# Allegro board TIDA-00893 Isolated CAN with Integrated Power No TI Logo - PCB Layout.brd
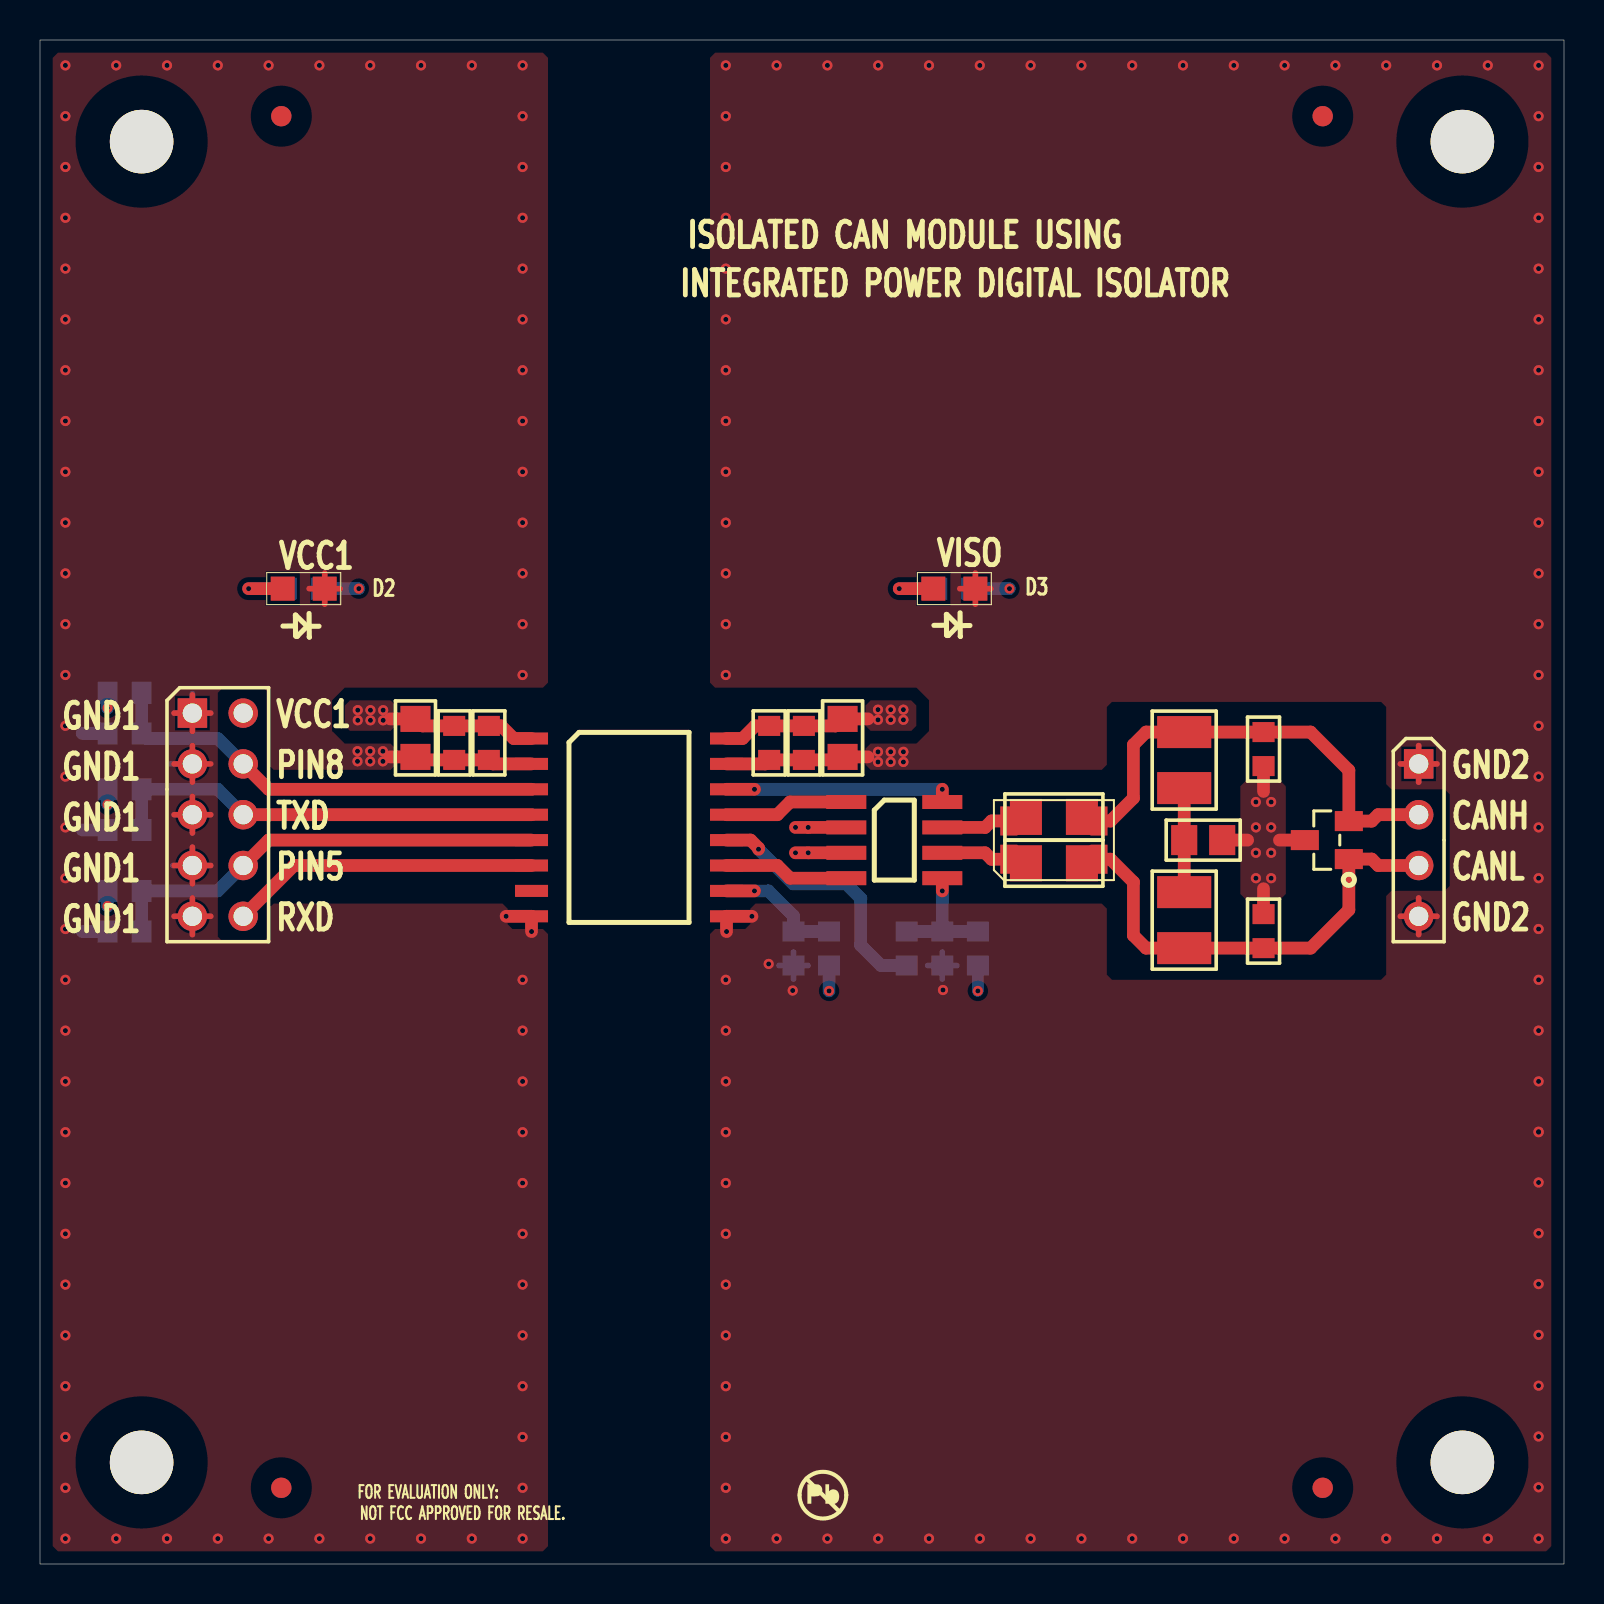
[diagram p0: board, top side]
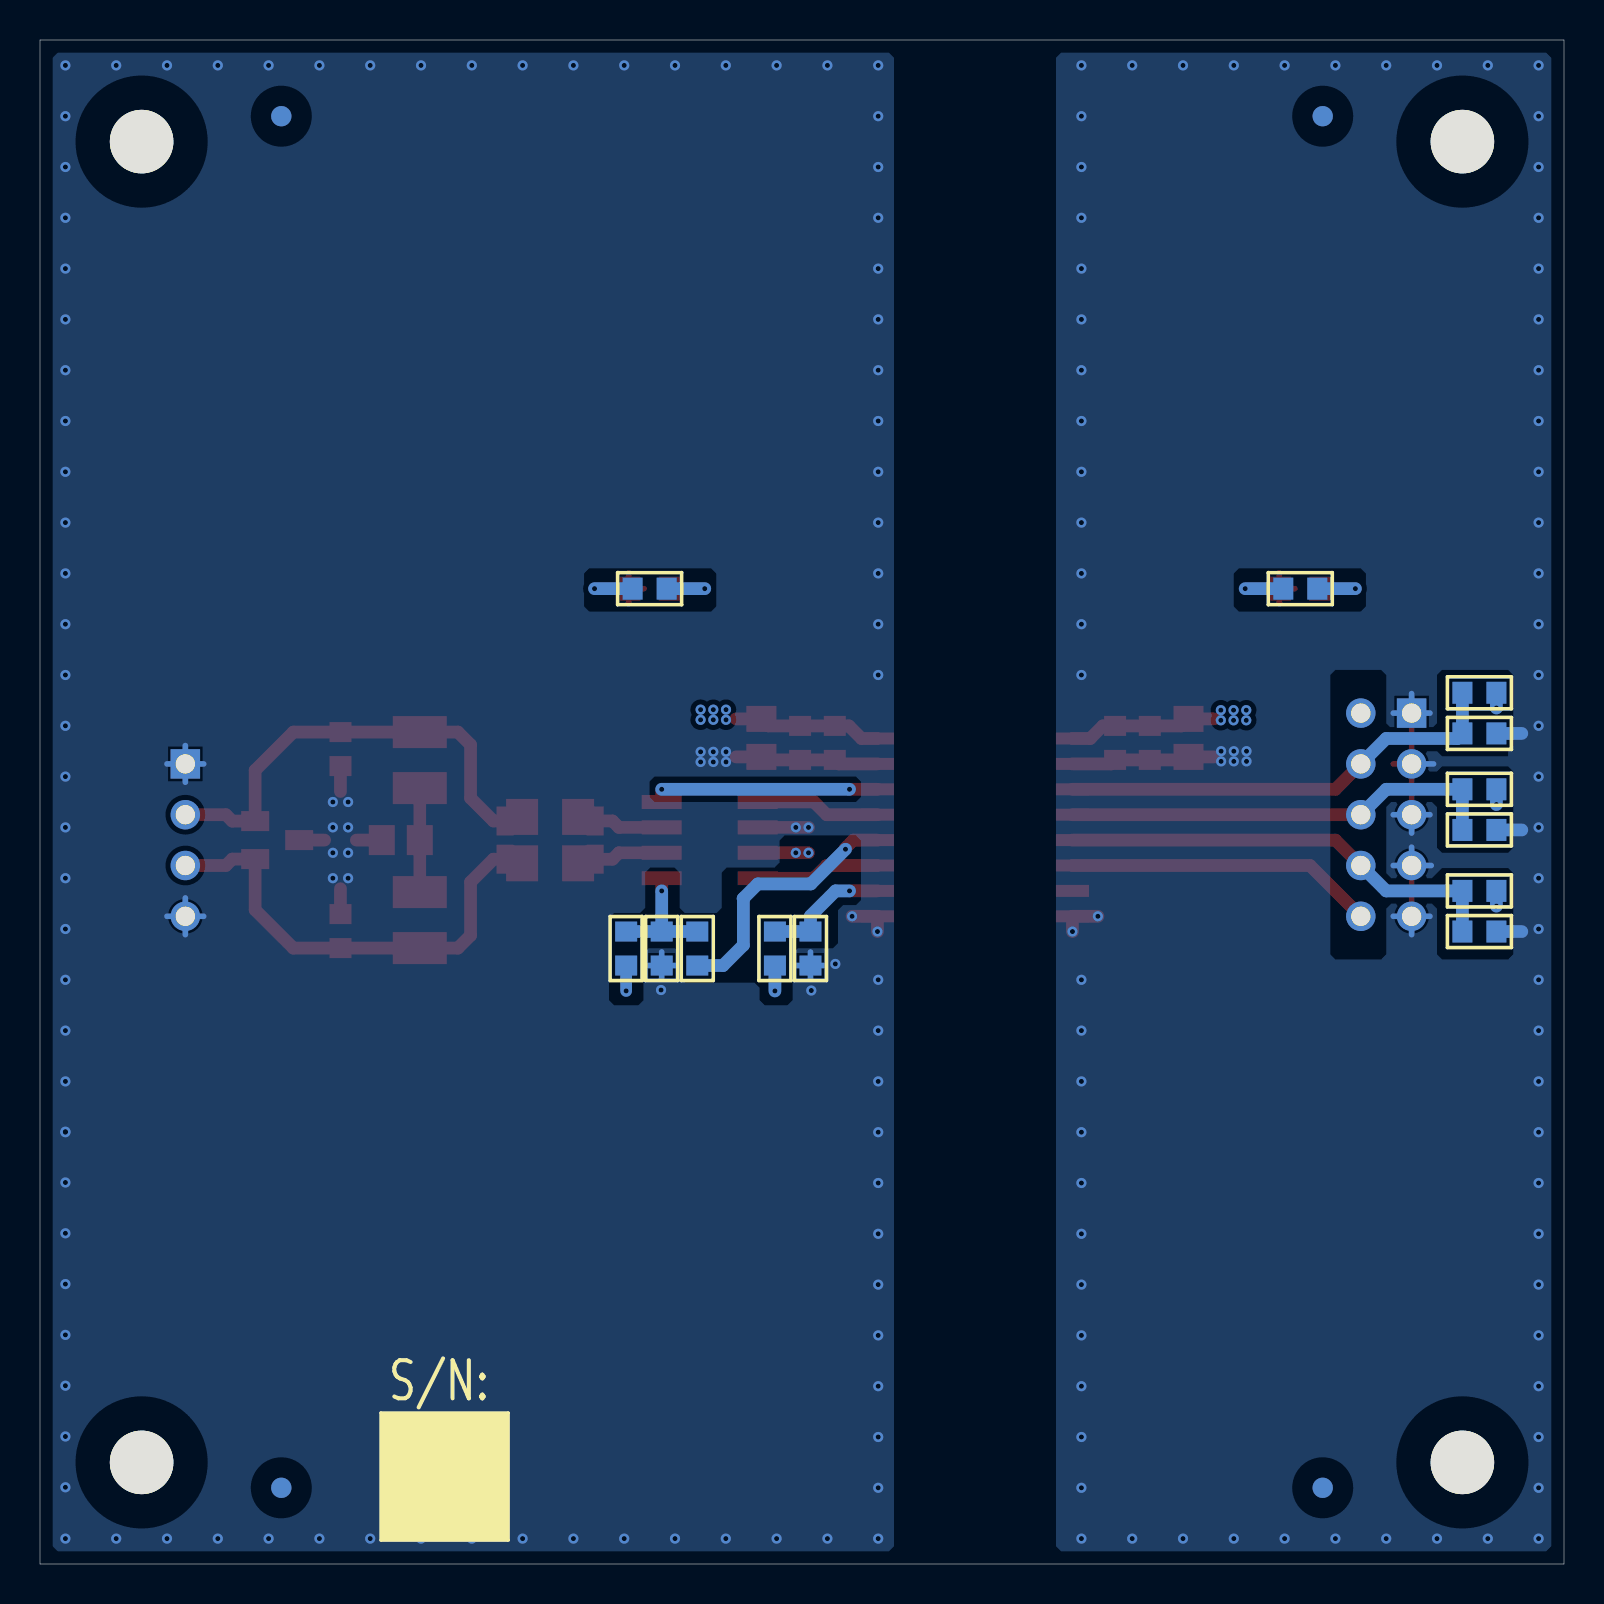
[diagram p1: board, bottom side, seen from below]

Outline 76.2 x 76.2 mm; copper layers: TOP, L2_GND, L3_PWR, BOTTOM. Coordinates in mm from the lower left corner of the outline.
Outline path: 0,76.2 76.2,76.2 76.2,0 0,0 0,76.2

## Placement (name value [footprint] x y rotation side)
C1  10uF  [0805]  18.77 42.25 270 top
C2  1uF  [0603]  20.71 40.2 90 top
C3  .1uF  [0603]  22.44 41.9 270 top
C4  10uF  [0805]  40.13 42.25 270 top
C5  1uF  [0603]  38.19 40.2 90 top
C6  DNI  [0603]  61.18 39.9 90 top
C7  0.1uF  [0603]  36.46 40.2 90 top
C8  0.1uF  [0805]  59.11 36.2 180 top
C9  DNI  [0603]  61.18 32.49 270 top
C10  0.1uF  [0603]  45.12 31.62 270 bottom
D1  DNI  [SOT23]  64.34 36.2 90 top
D2  GREEN  [LED_HSMB_C170DRA]  14.24 48.77 180 top
D3  GREEN  [LED_HSMB_C170DRA]  46.77 48.77 180 top
JMP1  Header 5x2  [HDR_THVT_2X5_100]  7.62 42.55 0 top
JMP2  HEADER 4X1  [HDR_THVT_1X4_100]  68.93 40.01 0 top
L1  DNI-CHOKE CM  [M2022_COMMON-MODE_CHOKE]  50.69 36.2 90 top
NOREF  -  []  0 0 0 top
NOREF#2  -  [unnamed#2]  71.12 71.12 0 top
NOREF#3  -  []  0 0 0 top
NOREF#4  -  []  39.17 3.47 0 top
NOREF#5  -  [unnamed#2]  64.14 3.81 0 top
NOREF#6  -  [unnamed#2]  12.06 3.81 0 top
NOREF#7  -  [unnamed#2]  5.08 5.08 0 top
NOREF#8  -  []  0 0 90 top
NOREF#9  -  [unnamed#2]  12.06 72.39 0 top
NOREF#10  -  [unnamed#2]  5.08 71.12 0 top
NOREF#11  -  []  54.8 6.96 0 top
NOREF#12  -  [unnamed#2]  64.14 72.39 0 top
NOREF#13  -  [unnamed#2]  71.12 5.08 0 top
NOREF#14  -  []  66.13 4.37 180 bottom
NOREF#15  -  [unnamed#2]  64.14 3.81 180 bottom
NOREF#16  -  [unnamed#2]  12.06 72.39 180 bottom
NOREF#17  -  [unnamed#2]  12.06 3.81 180 bottom
NOREF#18  -  [unnamed#2]  64.14 72.39 180 bottom
R1  4.99K  [0603]  5.08 43.56 180 bottom
R2  4.99K  [0603]  5.08 38.73 180 bottom
R3  4.99K  [0603]  5.08 33.66 180 bottom
R4  0-Ohm  [1206]  49.29 37.35 0 top
R5  60  [1210]  57.21 38.8 90 top
R6  60  [1210]  57.21 33.59 270 top
R7  DNI  [0603]  3.38 41.53 0 bottom
R8  DNI  [0603]  3.38 36.7 0 bottom
R9  DNI  [0603]  3.38 31.62 0 bottom
R10  0-Ohm  [0603]  39.45 31.62 270 bottom
R11  0-Ohm  [1206]  49.29 35.04 0 top
R12  DNI  [0603]  43.34 29.92 90 bottom
R13  DNI_0  [0603]  37.68 31.62 270 bottom
R14  0-Ohm  [0603]  46.89 29.92 90 bottom
R15  250  [0603]  14.04 48.77 180 bottom
R16  250  [0603]  46.57 48.77 180 bottom
U1  ISOW7841DWR  [DW0016BHV]  29.45 36.83 0 top
U2  TCAN1042  [D8]  42.72 36.2 0 top

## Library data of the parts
C1-C10 = C
D1 = MMBD101LT1_Diode_0
D2 D3 = LED_HSMS
JMP1 = Header 5x2
JMP2 = 4 Pin Berg Jumper
L1 = CHOKE CM14
R1-R14 = R
R15 R16 = r0402
U1 = ISOW7841DWR
U2 = TCAN1042

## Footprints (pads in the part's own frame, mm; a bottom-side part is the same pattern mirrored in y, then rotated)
0603
  rect 1x1.1 smd: 1(0,0) 2(1.7,0)
0805
  rect 1.3x1.5 smd: 1(0,0) 2(1.9,0)
1206
  rect 1.6x1.8 smd: 1(0,0) 2(2.8,0)
1210
  rect 1.6x2.7 smd: 1(0,0) 2(2.8,0)
D8
  rect 2x0.7 smd: 1(-2.4,1.905) 2(-2.4,0.635) 3(-2.4,-0.635) 4(-2.4,-1.905) 5(2.4,-1.905) 6(2.4,-0.635) 7(2.4,0.635) 8(2.4,1.905)
DW0016BHV
  rect 1.65x0.6 smd: 1(-4.875,4.445) 2(-4.875,3.175) 3(-4.875,1.905) 4(-4.875,0.635) 5(-4.875,-0.635) 6(-4.875,-1.905) 7(-4.875,-3.175) 8(-4.875,-4.445) 9(4.875,-4.445) 10(4.875,-3.175) 11(4.875,-1.905) 12(4.875,-0.635) 13(4.875,0.635) 14(4.875,1.905) 15(4.875,3.175) 16(4.875,4.445)
HDR_THVT_1X4_100
  rect 1.473x1.473 hole 0.965: 1(0,0)
  round 1.473 hole 0.965: 2(0,-2.54) 3(0,-5.08) 4(0,-7.62)
HDR_THVT_2X5_100
  rect 1.473x1.473 hole 0.965: 1(0,0)
  round 1.473 hole 0.965: 2(2.54,0) 3(0,-2.54) 4(2.54,-2.54) 5(0,-5.08) 6(2.54,-5.08) 7(0,-7.62) 8(2.54,-7.62) 9(0,-10.16) 10(2.54,-10.16)
LED_HSMB_C170DRA
  rect 1.2x1.2 smd: 1(0,0) 2(2.1,0)
M2022_COMMON-MODE_CHOKE
  custom 0.305x0.305 smd: 1(-0.955,2.07) 2(-0.955,-2.07) 3(0.955,-2.07) 4(0.955,2.07)
SOT23
  rect 1x1.4 smd: 1(-0.95,-1.1) 2(0.95,-1.1) 3(0,1.1)
unnamed#2
  round 3.175 hole 3.175 unplated: (0,0)

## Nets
GND_AC: C1.2 C2.1 C3.2 D2.1 JMP1.1 JMP1.3 JMP1.5 JMP1.7 JMP1.9 R7.1 R8.1 R9.1 U1.2(GND1_1) U1.8(GND1_2)
VCC1: C1.1 C2.2 C3.1 JMP1.2 R1.2 R2.2 R3.2 R15.1 U1.1(VCC1)
VCC1_LED: D2.2 R15.2
CAN_PIN5: C10.1 R12.2 R14.2 U2.5(NC/VIO)
CANH: L1.4 R4.1 U2.7(CANH)
CANH_BUS: C6.2 D1.2(NC) JMP2.2 L1.3 R4.2 R5.2
CANL: L1.1 R11.1 U2.6(CANL)
CANL_BUS: C9.2 D1.1(A) JMP2.3 L1.2 R6.2 R11.2
ISO-PIN5: R12.1 U1.12(OUTC)
ISO-PIN8: U1.14(OUTA) U2.8(S/STB)
ISO-RXD: JMP1.10 U1.6(OUTD)
ISO-TXD: U1.13(OUTB) U2.1(TXD)
PIN5: JMP1.8 R3.1 R9.2 U1.5(INC)
PIN8: JMP1.4 R1.1 R7.2 U1.3(INA)
RXD: U1.11(IND) U2.4(RXD)
SIGNAL_GND_AC: C4.2 C5.1 C6.1 C7.1 C8.1 C9.1 C10.2 D1.3(C) D3.1 JMP2.1 JMP2.4 R13.2 U1.9(GND2_2) U1.15(GND2_1) U2.2(GND)
SPLIT_TERM: C8.2 R5.1 R6.1
TXD: JMP1.6 R2.1 R8.2 U1.4(INB)
VISO: C4.1 C5.2 C7.2 R10.2 R14.1 R16.1 U1.16(VISO) U2.3(VCC)
VISO_LED: D3.2 R16.2
VSEL: R10.1 R13.1 U1.10(SEL)

Pads without a net: U1 7

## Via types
v1: diameter 0.508, hole 0.254, TOP to BOTTOM, 214 vias

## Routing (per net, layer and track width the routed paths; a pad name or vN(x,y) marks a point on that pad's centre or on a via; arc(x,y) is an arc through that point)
GND_AC: length 65
  TOP w0.279: 6.71,40.01 JMP1.3 ; JMP1.3 8.53,40.01 ; JMP1.3 7.62,40.92 ; JMP1.3 7.62,39.09 ; 13.46,48.77 D2.1 ; D2.1 15.01,48.77 ; D2.1 14.24,49.55 ; D2.1 14.24,47.99 ; 6.71,34.92 7.62,34.92 ; 7.62,34.92 7.62,35.84 ; 7.62,34.92 8.53,34.92 ; 7.62,34.92 7.62,34.01 ; 7.62,41.63 JMP1.1 ; JMP1.1 7.62,43.46 ; JMP1.1 6.71,42.55 ; JMP1.1 8.53,42.55 ; 7.62,32.38 8.53,32.38 ; 7.62,32.38 6.71,32.38 ; 7.62,32.38 7.62,31.47 ; 7.62,32.38 7.62,33.3 ; JMP1.5 7.62,38.38 ; JMP1.5 6.71,37.47 ; JMP1.5 7.62,36.55 ; JMP1.5 8.53,37.47
  TOP w0.635: U1.2 22.64,40.01 C3.2 C2.1 18.92,40.2 C1.2 17.5,40.36 ; v1(23.31,32.38) U1.8 v1(24.58,31.62)
  L2_GND w0.279: 7.62,32.38 8.53,32.38 ; 7.62,32.38 7.62,31.47 ; 7.62,32.38 6.71,32.38 ; 7.62,32.38 7.62,33.3 ; 6.71,37.47 JMP1.5 ; JMP1.5 7.62,38.38 ; JMP1.5 8.53,37.47 ; JMP1.5 7.62,36.55 ; JMP1.3 8.53,40.01 ; JMP1.3 7.62,40.92 ; JMP1.3 6.71,40.01 ; JMP1.3 7.62,39.09 ; 7.62,41.63 JMP1.1 ; JMP1.1 8.53,42.55 ; JMP1.1 7.62,43.46 ; JMP1.1 6.71,42.55 ; 7.62,34.92 8.53,34.92 ; 7.62,34.92 7.62,35.84 ; 7.62,34.92 7.62,34.01 ; 7.62,34.92 6.71,34.92
  BOTTOM w0.279: 6.71,42.55 JMP1.1 ; JMP1.1 8.53,42.55 ; JMP1.1 7.62,43.52 ; JMP1.5 8.53,37.47 ; JMP1.5 6.71,37.47 ; JMP1.5 7.62,36.55 ; JMP1.3 6.52,40.01 ; 7.62,31.47 7.62,32.38 ; 7.62,32.38 8.53,32.38 ; 7.62,32.38 6.71,32.38 ; 7.62,34.92 6.64,34.92 ; 7.62,34.92 7.62,35.84 ; 7.62,34.92 8.53,34.92
  BOTTOM w0.635: R7.1 2.11,41.53 ; R9.1 2.11,31.62 ; R8.1 2.11,36.7
  vias: v1(1.27,74.93) v1(1.27,72.39) v1(1.27,69.85) v1(1.27,67.31) v1(1.27,64.77) v1(1.27,62.23) v1(1.27,59.69) v1(1.27,57.15) v1(1.27,54.61) v1(1.27,52.07) v1(1.27,49.53) v1(1.27,46.99) v1(1.27,44.45) v1(1.27,41.91) v1(1.27,39.37) v1(1.27,36.83) v1(1.27,34.29) v1(1.27,31.75) v1(1.27,29.21) v1(1.27,26.67) v1(1.27,24.13) v1(1.27,21.59) v1(1.27,19.05) v1(1.27,16.51) v1(1.27,13.97) v1(1.27,11.43) v1(1.27,8.89) v1(1.27,6.35) v1(1.27,3.81) v1(1.27,1.27) v1(3.81,74.93) v1(3.81,1.27) v1(6.35,74.93) v1(6.35,1.27) v1(8.89,74.93) v1(8.89,1.27) v1(11.43,74.93) v1(11.43,1.27) v1(13.97,74.93) v1(13.97,1.27) v1(15.88,40.64) v1(15.88,40.13) v1(16.51,74.93) v1(16.51,40.64) v1(16.51,40.13) v1(16.51,1.27) v1(17.14,40.64) v1(17.14,40.13) v1(19.05,74.93) v1(19.05,1.27) v1(21.59,74.93) v1(21.59,1.27) v1(24.13,74.93) v1(24.13,72.39) v1(24.13,69.85) v1(24.13,67.31) v1(24.13,64.77) v1(24.13,62.23) v1(24.13,59.69) v1(24.13,57.15) v1(24.13,54.61) v1(24.13,52.07) v1(24.13,49.53) v1(24.13,46.99) v1(24.13,44.45) v1(24.13,29.21) v1(24.13,26.67) v1(24.13,24.13) v1(24.13,21.59) v1(24.13,19.05) v1(24.13,16.51) v1(24.13,13.97) v1(24.13,11.43) v1(24.13,8.89) v1(24.13,6.35) v1(24.13,3.81) v1(24.13,1.27)
VCC1: length 15.3
  TOP w0.635: 17.5,42.25 C1.1 19.12,41.9 C2.2 C3.1 23.06,41.9 23.69,41.27 U1.1
  L3_PWR w0.279: 10.16,41.63 JMP1.2 ; JMP1.2 11.07,42.55 ; JMP1.2 9.25,42.55 ; JMP1.2 10.16,43.46
  BOTTOM w0.635: v1(3.38,32.89) R3.2 ; v1(3.38,37.97) R2.2 ; v1(3.38,42.8) R1.2 ; R15.1 v1(15.94,48.77)
  vias: v1(15.89,42.69) v1(15.89,42.18) v1(16.52,42.69) v1(16.52,42.18) v1(17.16,42.69) v1(17.16,42.18)
VCC1_LED: length 3.6
  TOP w0.635: D2.2 v1(10.43,48.77)
  BOTTOM w0.635: R15.2 v1(10.43,48.77)
CAN_PIN5: length 6.2
  TOP w0.635: v1(45.12,33.66) U2.5
  BOTTOM w0.635: C10.1 v1(45.12,33.66) ; C10.1 R12.2 ; C10.1 R14.2
CANH: length 4.4
  TOP w0.635: U2.7 47.25,36.83 47.58,37.15 48.62,37.15 L1.4 48.83,37.35 R4.1
CANH_BUS: length 23.8
  TOP w0.635: JMP2.2 66.91,37.47 66.59,37.14 D1.2 65.44,39.68 63.53,41.6 C6.2 R5.2 55.31,41.6 54.67,40.96 54.67,38.29 53.53,37.15 L1.3 52.56,37.35 R4.2
CANL: length 4.4
  TOP w0.635: R11.1 48.83,35.04 L1.1 48.62,35.24 47.58,35.24 47.25,35.56 U2.6
CANL_BUS: length 23.8
  TOP w0.635: R11.2 52.56,35.04 L1.2 53.53,35.24 54.67,34.1 54.67,31.43 55.31,30.79 R6.2 C9.2 63.53,30.79 65.44,32.71 D1.1 66.59,35.25 66.91,34.92 68.93,34.92
ISO-PIN5: length 13
  TOP w0.635: v1(35.93,35.74) 35.93,35.8 35.53,36.2 U1.12
  BOTTOM w0.635: v1(35.93,35.74) 37.66,34 40.31,34 41.04,33.27 41.03,33.26 41.03,30.94 42.05,29.92 R12.1
ISO-PIN8: length 11.4
  TOP w0.635: U1.14 v1(35.72,38.73) ; U2.8 v1(45.12,38.73)
  BOTTOM w0.635: v1(35.72,38.73) v1(45.12,38.73)
ISO-RXD: length 15.5
  TOP w0.635: U1.6 12.7,34.92 10.16,32.38
ISO-TXD: length 6.3
  TOP w0.635: U1.13 36.87,37.47 37.5,38.1 U2.1
PIN5: length 22.6
  TOP w0.635: 10.16,34.92 11.43,36.2 U1.5
  BOTTOM w0.635: 10.16,34.92 8.89,33.66 R3.1 R9.2
PIN8: length 22.7
  TOP w0.635: U1.3 11.43,38.73 JMP1.4
  BOTTOM w0.635: JMP1.4 8.89,41.27 5.33,41.27 R7.2 R1.1
RXD: length 6.3
  TOP w0.635: U2.4 37.5,34.29 36.87,34.92 U1.11
SIGNAL_GND_AC: length 47.6
  TOP w0.279: D3.1 46.77,49.55 ; D3.1 46.77,47.99 ; D3.1 45.99,48.77 ; D3.1 47.55,48.77 ; 68.02,32.38 68.93,32.38 ; 68.93,32.38 68.93,31.47 ; 68.93,32.38 68.93,33.3 ; 68.93,32.38 69.85,32.38 ; JMP2.1 69.85,40.01 ; JMP2.1 68.93,39.09 ; JMP2.1 68.93,40.92 ; JMP2.1 68.02,40.01
  TOP w0.635: v1(35.6,32.38) U1.9 v1(34.33,31.62) ; D1.3 61.97,36.2 ; C6.1 61.18,38.63 ; U2.2 v1(38.41,36.83) v1(37.78,36.83) ; U1.15 36.26,40.01 C7.1 C5.1 39.98,40.2 C4.2 41.4,40.36 ; C8.1 60.38,36.2 ; C9.1 61.18,33.76
  L2_GND w0.279: JMP2.1 68.93,40.92 ; JMP2.1 69.85,40.01 ; JMP2.1 68.93,39.09 ; JMP2.1 68.02,40.01 ; 68.02,32.38 68.93,32.38 ; 68.93,32.38 69.85,32.38 ; 68.93,32.38 68.93,31.47 ; 68.93,32.38 68.93,33.3
  BOTTOM w0.279: JMP2.1 69.85,40.01 ; JMP2.1 68.02,40.01 ; JMP2.1 68.93,40.92 ; JMP2.1 68.93,39.09 ; C10.2 45.84,29.92 ; C10.2 45.12,30.6 ; C10.2 44.39,29.92 ; C10.2 45.12,29.24 ; 68.93,32.38 68.93,33.3 ; 68.93,32.38 68.93,31.47 ; 68.93,32.38 69.85,32.38 ; 68.93,32.38 68.02,32.38 ; R13.2 37.68,30.6 ; R13.2 36.95,29.92 ; R13.2 38.4,29.92 ; R13.2 37.68,29.24
  vias: v1(34.29,74.93) v1(34.29,72.39) v1(34.29,69.85) v1(34.29,67.31) v1(34.29,64.77) v1(34.29,62.23) v1(34.29,59.69) v1(34.29,57.15) v1(34.29,54.61) v1(34.29,52.07) v1(34.29,49.53) v1(34.29,46.99) v1(34.29,44.45) v1(34.29,29.21) v1(34.29,26.67) v1(34.29,24.13) v1(34.29,21.59) v1(34.29,19.05) v1(34.29,16.51) v1(34.29,13.97) v1(34.29,11.43) v1(34.29,8.89) v1(34.29,6.35) v1(34.29,3.81) v1(34.29,1.27) v1(36.43,30) v1(36.83,74.93) v1(36.83,1.27) v1(37.64,28.67) v1(39.37,74.93) v1(39.37,1.27) v1(41.91,74.93) v1(41.9,40.61) v1(41.9,40.1) v1(41.91,1.27) v1(42.53,40.61) v1(42.53,40.1) v1(43.17,40.61) v1(43.17,40.1) v1(44.45,74.93) v1(44.45,1.27) v1(45.15,28.7) v1(46.99,74.93) v1(46.99,1.27) v1(49.53,74.93) v1(49.53,1.27) v1(52.07,74.93) v1(52.07,1.27) v1(54.61,74.93) v1(54.61,1.27) v1(57.15,74.93) v1(57.15,1.27) v1(59.69,74.93) v1(59.69,1.27) v1(60.8,38.1) v1(60.8,36.83) v1(60.8,35.56) v1(60.8,34.29) v1(61.56,38.1) v1(61.56,36.83) v1(61.56,35.56) v1(61.56,34.29) v1(62.23,74.93) v1(62.23,1.27) v1(64.77,74.93) v1(64.77,1.27) v1(67.31,74.93) v1(67.31,1.27) v1(69.85,74.93) v1(69.85,1.27) v1(72.39,74.93) v1(72.39,1.27) v1(74.93,74.93) v1(74.93,72.39) v1(74.93,69.85) v1(74.93,67.31) v1(74.93,64.77) v1(74.93,62.23) v1(74.93,59.69) v1(74.93,57.15) v1(74.93,54.61) v1(74.93,52.07) v1(74.93,49.53) v1(74.93,46.99) v1(74.93,44.45) v1(74.93,41.91) v1(74.93,39.37) v1(74.93,36.83) v1(74.93,34.29) v1(74.93,31.75) v1(74.93,29.21) v1(74.93,26.67) v1(74.93,24.13) v1(74.93,21.62) v1(74.93,21.59) v1(74.93,19.08) v1(74.93,16.54) v1(74.93,14) v1(74.93,11.46) v1(74.93,8.92) v1(74.93,6.38) v1(74.93,3.84) v1(74.93,1.27)
SPLIT_TERM: length 5.2
  TOP w0.635: R6.1 C8.2 R5.1
TXD: length 22.1
  TOP w0.635: U1.4 JMP1.6
  BOTTOM w0.635: JMP1.6 8.89,38.73 R2.1 R8.2
VISO: length 14.5
  TOP w0.635: U2.3 v1(38.41,35.56) v1(37.78,35.56) ; 41.4,42.25 C4.1 39.78,41.9 C5.2 C7.2 35.76,41.9 35.13,41.27 U1.16
  BOTTOM w0.584: R14.1 v1(46.89,28.65)
  BOTTOM w0.635: v1(39.45,28.65) R10.2 ; R16.1 v1(48.47,48.77)
  vias: v1(41.9,42.72) v1(41.9,42.21) v1(42.53,42.72) v1(42.53,42.21) v1(43.17,42.72) v1(43.17,42.21)
VISO_LED: length 3.6
  TOP w0.635: D3.2 v1(42.96,48.77)
  BOTTOM w0.635: R16.2 v1(42.96,48.77)
VSEL: length 6.4
  TOP w0.635: v1(35.72,33.66) U1.10
  BOTTOM w0.635: R10.1 R13.1 37.68,32.4 36.42,33.66 v1(35.72,33.66)

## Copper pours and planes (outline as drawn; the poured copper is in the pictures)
GND_AC on TOP: 0.89,0.64 0.64,0.89 0.64,75.31 0.89,75.56 25.15,75.56 25.4,75.31 25.4,44.07 25.15,43.81 16.09,43.81 16.09,41.02 17.53,41.02 17.78,40.77 17.78,39.96 17.53,39.71 11.68,39.71 11.43,39.96 11.43,43.56 11.18,43.81 9.14,43.81 8.89,43.56 8.89,31.37 9.14,31.11 11.18,31.11 11.43,31.37 11.43,32.77 11.68,33.02 23.13,33.02 23.38,32.77 23.38,31.99 23.62,31.75 25.15,31.75 25.4,31.5 25.4,0.89 25.15,0.64
GND_AC on BOTTOM: 0.89,0.64 0.64,0.89 0.64,75.31 0.89,75.56 25.15,75.56 25.4,75.31 25.4,0.89 25.15,0.64 ; 2 cut-outs
GND_AC on L2_GND: 0.89,0.64 0.64,0.89 0.64,75.31 0.89,75.56 25.15,75.56 25.4,75.31 25.4,73.91 25.65,73.66 32.59,73.66 32.84,73.41 32.84,2.79 32.59,2.54 25.65,2.54 25.4,2.29 25.4,0.89 25.15,0.64
VCC1 on TOP: 15.49,41.66 17.53,41.66 17.78,41.91 17.78,42.93 17.53,43.18 15.49,43.18 15.24,42.93 15.24,41.91
VCC1 on L3_PWR: 0.89,0.64 25.15,0.64 25.4,0.89 25.4,75.31 25.15,75.56 0.89,75.56 0.64,75.31 0.64,0.89
SIGNAL_GND_AC on TOP: 60.27,33.25 62.03,33.25 62.29,33.5 62.29,38.89 62.03,39.14 60.27,39.14 60.02,38.89 60.02,33.5
SIGNAL_GND_AC on TOP: 33.75,0.64 33.5,0.89 33.5,31.5 33.75,31.75 35.26,31.75 35.52,32 35.52,32.77 35.77,33.02 53.09,33.02 53.34,32.77 53.34,29.46 53.59,29.21 67.06,29.21 67.31,29.46 67.31,33.4 67.56,33.66 70.23,33.66 70.48,33.91 70.48,38.48 70.23,38.73 67.56,38.73 67.31,38.99 67.31,42.85 67.06,43.1 53.59,43.1 53.34,42.85 53.34,39.96 53.09,39.71 41.53,39.71 41.27,39.96 41.27,40.77 41.53,41.02 42.55,41.02 42.55,43.81 33.75,43.81 33.5,44.07 33.5,75.31 33.75,75.56 75.31,75.56 75.56,75.31 75.56,0.89 75.31,0.64
SIGNAL_GND_AC on BOTTOM: 33.75,0.64 33.5,0.89 33.5,75.31 33.75,75.56 75.31,75.56 75.56,75.31 75.56,0.89 75.31,0.64 ; 3 cut-outs
SIGNAL_GND_AC on L2_GND: 33.75,0.64 75.31,0.64 75.56,0.89 75.56,75.31 75.31,75.56 33.75,75.56 33.5,75.31 33.5,0.89
VISO on TOP: 41.53,41.66 43.56,41.66 43.81,41.91 43.81,42.93 43.56,43.18 41.53,43.18 41.27,42.93 41.27,41.91
VISO on L3_PWR: 33.75,0.64 33.5,0.89 33.5,2.29 33.25,2.54 26.31,2.54 26.06,2.79 26.06,73.41 26.31,73.66 33.25,73.66 33.5,73.91 33.5,75.31 33.75,75.56 75.31,75.56 75.56,75.31 75.56,0.89 75.31,0.64

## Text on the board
BOTTOM: LAYER 4 - BOTTOM SIDE
Ref Des/Assembly Bottom: BOTTOM - ASSEMBLY
Board Geometry/Soldermask Bottom: SOLDERMASK BOTTOM
Package Geometry/Pastemask Bottom: PASTEMASK BOTTOM
Ref Des/Silkscreen Bottom: SILKSCREEN BOTTOM
User.Comments: IN (.XX)+/-0.01 (.XXX)+/-0.003 | MM (.XX)+/-0.01 (.XXX)+/-0.003 | FRACTION  +/- 1/32 | ANGLE  +/- 1.0 DEGREE | THIRD ANGLE PROJECTION | TOLERANCES | UNITS   IN (MM) | UNLESS OTHERWISE SPECIFIED | WWW.TI.COM | 12500 TI BLVD | DALLAS,TX 75243 | TEXAS INSTRUMENTS INC. | THIS DOCUMENT AND THE INFORMATION IN IT | BE DISCLOSED TO ANY THIRD PARTY OR USED | ARE PROVIDED IN CONFIDENCE, FOR THE SOLE | WRITTEN PERMISSION OF TEXAS INSTRUMENTS. | PURPOSE OF BOARD FABRICATION, AND MAY NOT | FOR ANY OTHER PURPOSE WITHOUT THE EXPRESS | TEXAS INSTRUMENTS CONFIDENTIAL
Board Geometry/Outline: BOARD OUTLINE
TOP: LAYER 1 - TOP SIDE
Ref Des/Assembly Top: TOP - ASSEMBLY
Board Geometry/Soldermask Top: SOLDERMASK TOP
Package Geometry/Pastemask Top: PASTEMASK TOP
Ref Des/Silkscreen Top: FOR EVALUATION ONLY: | NOT FCC APPROVED FOR RESALE. | VCC1 | VISO | ISOLATED CAN MODULE USING | INTEGRATED POWER DIGITAL ISOLATOR | SILKSCREEN TOP
L2_GND: LAYER 2 - GND
L3_PWR: LAYER 3 - PWR
XSECTION_CHART: *  SURFACE - AIR 0 MIL | *  DIELECTRIC - SOLDERMASK-0.8MIL 0.8 MIL | L1: TOP CONDUCTOR - 2OZ_COPPER 2.8 MIL | *  DIELECTRIC - FR-4 14 MIL | L2: L2_GND PLANE - 1OZ_COPPER 1.4 MIL | *  DIELECTRIC - FR-4 23.6 MIL | L3: L3_PWR PLANE - 1OZ_COPPER 1.4 MIL | L4: BOTTOM CONDUCTOR - 2OZ_COPPER 2.8 MIL | DESIGN CROSS SECTION CHART | ___________________________ | TOTAL THICKNESS 61.6 MIL | 1-4
PAGE_OUTLINE: J. NERGER | xxx | 01-16-17 | xx-xx-xx | DRAWN: | RELEASED: | DO NOT SCALE DRAWING | APPROVALS | DATE | SIZE | SCALE | CUSTOMER | ID NO. | NONE | JOB NO. | ENGINEER | REV. | TIDA-00893 | BOARD NAME : ISOWATT + TCAN | A | D | C | B | 8 | 7 | 6 | 5 | 4 | 3 | 2 | 1
DIMENSION: FABRICATION DRAWING | CAD ORIGIN
User.6: ALL ARTWORK LAYERS VIEWED FROM TOP | BOARD NAME: | ISOWATT + TCAN REFERENCE DESIGN | BOARD REV: | LAYER DESCRIPTION: | A | ID: | TIDA-00893 | JOB NUMBER:
User.8: LAYER 1 | LAYER 2 | LAYER 3 | LAYER 4 | LAYER | NO. | TABLE 1: | TOP | L2_GND | L3_PWR | BOTTOM | NAME | DIFFIRENTIAL PAIR | IMPEDANCE (OHMS) | DIFF TRACE | WIDTH | SINGLE ENDED | 50 OHMS | TRACE WIDTH | 25 MILS | REFERENCE | SPECIAL FAB NOTES: | 1:FAB SHOP MUST FOLLOW THE SOLDER MASK REVIEW LAYERS. | 2:ADJUSTMENTS MAY BE MADE TO THE DIELECTRIC THICKNESS AND SIGNAL TRACE WIDTH | IN ORDER TO MAINTAIN A TOTAL BOARD THICKNESS. | PLACE DRILL CHART HERE: | MIN. ANNULAR RING 2 MIL EXTERNAL PER IPC-6012C CLASS 2 | REGISTRATION TOLERANCES: METAL +/- X MIL,HOLES +/- X MIL | IMPEDANCE CONTROL: | BOARD SIZE (REFER ALSO ARRAY/PANEL PROFILING INFORMATION) | MIXED DIELECTRIC: | LAMINATE MATERIAL: | THICKNESS: | TOLERANCE: | COPPER THICKNESS (FINISHED): | BOARD FINISH: | NUMBER OF LAYERS: | MIN. TRACK WIDTH: | MIN. CLEARANCE  : | MIN. VIA PAD/DRILL: | THIEVING ALLOWED: | X | OUTER: | INNER SIGNAL: | INNER PLANE: | OTHER: | SILKSCREEN: | SOLDERMASK: (PER IPC-6011,6012) | BOARD SURFACE TREATMENT: | ADDITIONAL REQUIREMENTS: | VENDOR MARKING: | SILKSCREEN COLOR: | SOLDERMASK COLOR: | THROUGH-HOLE VIA TREATMENT: | VIA FILL USING NON-CONDUCTIVE EPOXY: | FOR WIRE BONDING: | VENDOR DATE CODE,UL,LOGO: | FR-4 HIGH Tg | 0.062" +/-10% | IPC-6012C TYPE 3 CLASS 2 | OTHER +/- | MICRO-SECTION | CERTIFICATES OF COMPLIANCE | NICKEL/GOLD (ENIG) | IMMERSION TIN | HARD GOLD | IN AN OPEN AREA | 1/4 OZ. | OPEN | NO | 4 | 11 MIL | X.X MIL | 20/10 MIL | NONE | DESIGN INFORMATION | ROGERS 4350B | 0.093" +/-10% | YES | TDR REPORTS/COUPONS | WHITE | GREEN | SOFT GOLD | TENTED | 1/2 OZ. | BOW & TWIST: | ORGANIC (OSP) | OTHER | WHERE INDICATED (SEE DRAWING) | YES - SEE TABLE 1 | ETCH | IDENTIFIER: | BLUE | RoHS | 1.0 OZ. | SILKSCREEN | PER SUPPLIED ARTWORK | ALL x MIL VIAS | ELECTRICAL TEST | UL 94V-0 | HASL | 2.0 OZ. | SHEET 1 OF 1 | BREAK-AWAY | ENEPIG | FABRICATION DRAWING
User.9: SHEET 1 OF 2 | ASSEMBLY DRAWING (TOP SIDE)
User.10: SHEET 2 OF 2 | ASSEMBLY DRAWING (BOTTOM SIDE)
User.18: FIGURE | SIZE | 10.0 | 38.0 | 125.0 | DRILL CHART: TOP to BOTTOM | ALL UNITS ARE IN MILS | TOLERANCE | +3.0/-10.0 | +0.0/-0.0 | +2.0/-2.0 | PLATED | NON-PLATED | QTY | 214 | 14 | 4
